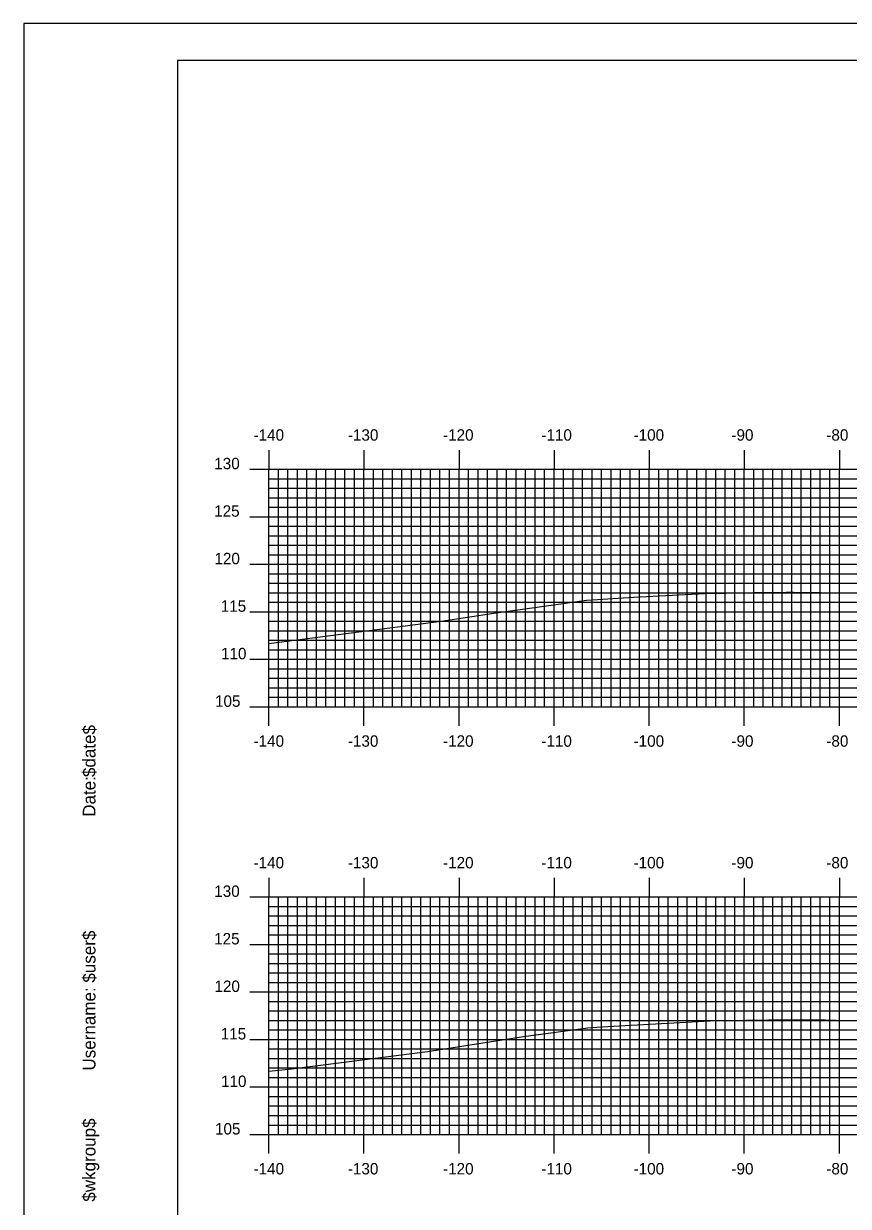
# Model space of a CAD drawing. Extents: x 855468 to 855811, y 366605 to 366825.
# Drawn here: x 855467.8 to 855554.5, y 366700.5 to 366824.9 of the extents above; entities that cross this region are included whole.
import ezdxf

# ---------------------------------------------------------------- set-up
doc = ezdxf.new("R2010")
doc.units = 0
for name, color, linetype in [('BORDER', 7, 'Continuous'), ('H_V ANNOTATION', 7, 'Continuous'), ('M_Roadway_Centerline', 7, 'Continuous'), ('MAJOR', 7, 'Continuous'), ('MINOR', 7, 'Continuous'), ('PLOT BOUNDARY', 7, 'Continuous'), ('S_Roadway_Centerline', 7, 'Continuous')]:
    doc.layers.add(name, color=color, linetype=linetype)

msp = doc.modelspace()

# ---------------------------------------------------------------- linework, layer by layer
at = {"layer": 'BORDER'}
msp.add_lwpolyline([(855483.98, 366611.06), (855803.98, 366611.06), (855803.98, 366821.06), (855483.98, 366821.06)], close=True, dxfattribs=at)
at = {"layer": 'MAJOR'}
for p, q in [((855493.58, 366780.06), (855493.58, 366778.06)), ((855503.58, 366780.06), (855503.58, 366778.06)), ((855513.58, 366780.06), (855513.58, 366778.06)), ((855523.58, 366780.06), (855523.58, 366778.06)), ((855533.58, 366780.06), (855533.58, 366778.06)), ((855543.58, 366780.06), (855543.58, 366778.06)), ((855553.58, 366780.06), (855553.58, 366778.06)), ((855491.58, 366778.06), (855493.58, 366778.06)), ((855493.58, 366778.06), (855773.58, 366778.06)), ((855493.58, 366753.06), (855493.58, 366778.06)), ((855493.58, 366753.06), (855493.58, 366778.06)), ((855493.58, 366778.06), (855773.58, 366778.06)), ((855503.58, 366753.06), (855503.58, 366778.06)), ((855513.58, 366753.06), (855513.58, 366778.06)), ((855523.58, 366753.06), (855523.58, 366778.06)), ((855533.58, 366753.06), (855533.58, 366778.06)), ((855543.58, 366753.06), (855543.58, 366778.06)), ((855553.58, 366753.06), (855553.58, 366778.06)), ((855491.58, 366773.06), (855493.58, 366773.06)), ((855493.58, 366773.06), (855773.58, 366773.06)), ((855491.58, 366768.06), (855493.58, 366768.06)), ((855493.58, 366768.06), (855773.58, 366768.06)), ((855491.58, 366763.06), (855493.58, 366763.06)), ((855493.58, 366763.06), (855773.58, 366763.06)), ((855491.58, 366758.06), (855493.58, 366758.06)), ((855493.58, 366758.06), (855773.58, 366758.06)), ((855491.58, 366753.06), (855493.58, 366753.06)), ((855493.58, 366753.06), (855773.58, 366753.06)), ((855493.58, 366753.06), (855773.58, 366753.06)), ((855493.58, 366751.05), (855493.58, 366753.06)), ((855503.58, 366751.05), (855503.58, 366753.06)), ((855513.58, 366751.05), (855513.58, 366753.06)), ((855523.58, 366751.05), (855523.58, 366753.06)), ((855533.58, 366751.05), (855533.58, 366753.06)), ((855543.58, 366751.05), (855543.58, 366753.06)), ((855553.58, 366751.05), (855553.58, 366753.06)), ((855493.58, 366735.06), (855493.58, 366733.06)), ((855503.58, 366735.06), (855503.58, 366733.06)), ((855513.58, 366735.06), (855513.58, 366733.06)), ((855523.58, 366735.06), (855523.58, 366733.06)), ((855533.58, 366735.06), (855533.58, 366733.06)), ((855543.58, 366735.06), (855543.58, 366733.06)), ((855553.58, 366735.06), (855553.58, 366733.06)), ((855491.58, 366733.06), (855493.58, 366733.06)), ((855493.58, 366733.06), (855773.58, 366733.06)), ((855493.58, 366708.06), (855493.58, 366733.06)), ((855493.58, 366708.06), (855493.58, 366733.06)), ((855493.58, 366733.06), (855773.58, 366733.06)), ((855503.58, 366708.06), (855503.58, 366733.06)), ((855513.58, 366708.06), (855513.58, 366733.06)), ((855523.58, 366708.06), (855523.58, 366733.06)), ((855533.58, 366708.06), (855533.58, 366733.06)), ((855543.58, 366708.06), (855543.58, 366733.06)), ((855553.58, 366708.06), (855553.58, 366733.06)), ((855491.58, 366728.06), (855493.58, 366728.06)), ((855493.58, 366728.06), (855773.58, 366728.06)), ((855491.58, 366723.06), (855493.58, 366723.06)), ((855493.58, 366723.06), (855773.58, 366723.06)), ((855491.58, 366718.06), (855493.58, 366718.06)), ((855493.58, 366718.06), (855773.58, 366718.06)), ((855491.58, 366713.06), (855493.58, 366713.06)), ((855493.58, 366713.06), (855773.58, 366713.06)), ((855491.58, 366708.06), (855493.58, 366708.06)), ((855493.58, 366708.06), (855773.58, 366708.06)), ((855493.58, 366708.06), (855773.58, 366708.06)), ((855493.58, 366706.05), (855493.58, 366708.06)), ((855503.58, 366706.05), (855503.58, 366708.06)), ((855513.58, 366706.05), (855513.58, 366708.06)), ((855523.58, 366706.05), (855523.58, 366708.06)), ((855533.58, 366706.05), (855533.58, 366708.06)), ((855543.58, 366706.05), (855543.58, 366708.06)), ((855553.58, 366706.05), (855553.58, 366708.06))]:
    msp.add_line(p, q, dxfattribs=at)
at = {"layer": 'MINOR'}
for p, q in [((855494.58, 366753.06), (855494.58, 366778.06)), ((855495.58, 366753.06), (855495.58, 366778.06)), ((855496.58, 366753.06), (855496.58, 366778.06)), ((855497.58, 366753.06), (855497.58, 366778.06)), ((855498.58, 366753.06), (855498.58, 366778.06)), ((855499.58, 366753.06), (855499.58, 366778.06)), ((855500.58, 366753.06), (855500.58, 366778.06)), ((855501.58, 366753.06), (855501.58, 366778.06)), ((855502.58, 366753.06), (855502.58, 366778.06)), ((855504.58, 366753.06), (855504.58, 366778.06)), ((855505.58, 366753.06), (855505.58, 366778.06)), ((855506.58, 366753.06), (855506.58, 366778.06)), ((855507.58, 366753.06), (855507.58, 366778.06)), ((855508.58, 366753.06), (855508.58, 366778.06)), ((855509.58, 366753.06), (855509.58, 366778.06)), ((855510.58, 366753.06), (855510.58, 366778.06)), ((855511.58, 366753.06), (855511.58, 366778.06)), ((855512.58, 366753.06), (855512.58, 366778.06)), ((855514.58, 366753.06), (855514.58, 366778.06)), ((855515.58, 366753.06), (855515.58, 366778.06)), ((855516.58, 366753.06), (855516.58, 366778.06)), ((855517.58, 366753.06), (855517.58, 366778.06)), ((855518.58, 366753.06), (855518.58, 366778.06)), ((855519.58, 366753.06), (855519.58, 366778.06)), ((855520.58, 366753.06), (855520.58, 366778.06)), ((855521.58, 366753.06), (855521.58, 366778.06)), ((855522.58, 366753.06), (855522.58, 366778.06)), ((855524.58, 366753.06), (855524.58, 366778.06)), ((855525.58, 366753.06), (855525.58, 366778.06)), ((855526.58, 366753.06), (855526.58, 366778.06)), ((855527.58, 366753.06), (855527.58, 366778.06)), ((855528.58, 366753.06), (855528.58, 366778.06)), ((855529.58, 366753.06), (855529.58, 366778.06)), ((855530.58, 366753.06), (855530.58, 366778.06)), ((855531.58, 366753.06), (855531.58, 366778.06)), ((855532.58, 366753.06), (855532.58, 366778.06)), ((855534.58, 366753.06), (855534.58, 366778.06)), ((855535.58, 366753.06), (855535.58, 366778.06)), ((855536.58, 366753.06), (855536.58, 366778.06)), ((855537.58, 366753.06), (855537.58, 366778.06)), ((855538.58, 366753.06), (855538.58, 366778.06)), ((855539.58, 366753.06), (855539.58, 366778.06)), ((855540.58, 366753.06), (855540.58, 366778.06)), ((855541.58, 366753.06), (855541.58, 366778.06)), ((855542.58, 366753.06), (855542.58, 366778.06)), ((855544.58, 366753.06), (855544.58, 366778.06)), ((855545.58, 366753.06), (855545.58, 366778.06)), ((855546.58, 366753.06), (855546.58, 366778.06)), ((855547.58, 366753.06), (855547.58, 366778.06)), ((855548.58, 366753.06), (855548.58, 366778.06)), ((855549.58, 366753.06), (855549.58, 366778.06)), ((855550.58, 366753.06), (855550.58, 366778.06)), ((855551.58, 366753.06), (855551.58, 366778.06)), ((855552.58, 366753.06), (855552.58, 366778.06)), ((855493.58, 366777.06), (855773.58, 366777.06)), ((855493.58, 366777.06), (855495.59, 366777.06)), ((855493.58, 366776.06), (855773.58, 366776.06)), ((855493.58, 366776.06), (855495.59, 366776.06)), ((855493.58, 366775.06), (855773.58, 366775.06)), ((855493.58, 366775.06), (855495.59, 366775.06)), ((855493.58, 366774.06), (855773.58, 366774.06)), ((855493.58, 366774.06), (855495.59, 366774.06)), ((855493.58, 366772.06), (855773.58, 366772.06)), ((855493.58, 366772.06), (855495.59, 366772.06)), ((855493.58, 366771.06), (855773.58, 366771.06)), ((855493.58, 366771.06), (855495.59, 366771.06)), ((855493.58, 366770.06), (855773.58, 366770.06)), ((855493.58, 366770.06), (855495.59, 366770.06)), ((855493.58, 366769.06), (855773.58, 366769.06)), ((855493.58, 366769.06), (855495.59, 366769.06)), ((855493.58, 366767.06), (855773.58, 366767.06)), ((855493.58, 366767.06), (855495.59, 366767.06)), ((855493.58, 366766.06), (855773.58, 366766.06)), ((855493.58, 366766.06), (855495.59, 366766.06)), ((855493.58, 366765.06), (855773.58, 366765.06)), ((855493.58, 366765.06), (855495.59, 366765.06)), ((855493.58, 366764.06), (855773.58, 366764.06)), ((855493.58, 366764.06), (855495.59, 366764.06)), ((855493.58, 366762.06), (855773.58, 366762.06)), ((855493.58, 366762.06), (855495.59, 366762.06)), ((855493.58, 366761.06), (855773.58, 366761.06)), ((855493.58, 366761.06), (855495.59, 366761.06)), ((855493.58, 366760.06), (855773.58, 366760.06)), ((855493.58, 366760.06), (855495.59, 366760.06)), ((855493.58, 366759.06), (855773.58, 366759.06)), ((855493.58, 366759.06), (855495.59, 366759.06)), ((855493.58, 366757.06), (855773.58, 366757.06)), ((855493.58, 366757.06), (855495.59, 366757.06)), ((855493.58, 366756.06), (855773.58, 366756.06)), ((855493.58, 366756.06), (855495.59, 366756.06)), ((855493.58, 366755.06), (855773.58, 366755.06)), ((855493.58, 366755.06), (855495.59, 366755.06)), ((855493.58, 366754.06), (855773.58, 366754.06)), ((855493.58, 366754.06), (855495.59, 366754.06)), ((855494.58, 366708.06), (855494.58, 366733.06)), ((855495.58, 366708.06), (855495.58, 366733.06)), ((855496.58, 366708.06), (855496.58, 366733.06)), ((855497.58, 366708.06), (855497.58, 366733.06)), ((855498.58, 366708.06), (855498.58, 366733.06)), ((855499.58, 366708.06), (855499.58, 366733.06)), ((855500.58, 366708.06), (855500.58, 366733.06)), ((855501.58, 366708.06), (855501.58, 366733.06)), ((855502.58, 366708.06), (855502.58, 366733.06)), ((855504.58, 366708.06), (855504.58, 366733.06)), ((855505.58, 366708.06), (855505.58, 366733.06)), ((855506.58, 366708.06), (855506.58, 366733.06)), ((855507.58, 366708.06), (855507.58, 366733.06)), ((855508.58, 366708.06), (855508.58, 366733.06)), ((855509.58, 366708.06), (855509.58, 366733.06)), ((855510.58, 366708.06), (855510.58, 366733.06)), ((855511.58, 366708.06), (855511.58, 366733.06)), ((855512.58, 366708.06), (855512.58, 366733.06)), ((855514.58, 366708.06), (855514.58, 366733.06)), ((855515.58, 366708.06), (855515.58, 366733.06)), ((855516.58, 366708.06), (855516.58, 366733.06)), ((855517.58, 366708.06), (855517.58, 366733.06)), ((855518.58, 366708.06), (855518.58, 366733.06)), ((855519.58, 366708.06), (855519.58, 366733.06)), ((855520.58, 366708.06), (855520.58, 366733.06)), ((855521.58, 366708.06), (855521.58, 366733.06)), ((855522.58, 366708.06), (855522.58, 366733.06)), ((855524.58, 366708.06), (855524.58, 366733.06)), ((855525.58, 366708.06), (855525.58, 366733.06)), ((855526.58, 366708.06), (855526.58, 366733.06)), ((855527.58, 366708.06), (855527.58, 366733.06)), ((855528.58, 366708.06), (855528.58, 366733.06)), ((855529.58, 366708.06), (855529.58, 366733.06)), ((855530.58, 366708.06), (855530.58, 366733.06)), ((855531.58, 366708.06), (855531.58, 366733.06)), ((855532.58, 366708.06), (855532.58, 366733.06)), ((855534.58, 366708.06), (855534.58, 366733.06)), ((855535.58, 366708.06), (855535.58, 366733.06)), ((855536.58, 366708.06), (855536.58, 366733.06)), ((855537.58, 366708.06), (855537.58, 366733.06)), ((855538.58, 366708.06), (855538.58, 366733.06)), ((855539.58, 366708.06), (855539.58, 366733.06)), ((855540.58, 366708.06), (855540.58, 366733.06)), ((855541.58, 366708.06), (855541.58, 366733.06)), ((855542.58, 366708.06), (855542.58, 366733.06)), ((855544.58, 366708.06), (855544.58, 366733.06)), ((855545.58, 366708.06), (855545.58, 366733.06)), ((855546.58, 366708.06), (855546.58, 366733.06)), ((855547.58, 366708.06), (855547.58, 366733.06)), ((855548.58, 366708.06), (855548.58, 366733.06)), ((855549.58, 366708.06), (855549.58, 366733.06)), ((855550.58, 366708.06), (855550.58, 366733.06)), ((855551.58, 366708.06), (855551.58, 366733.06)), ((855552.58, 366708.06), (855552.58, 366733.06)), ((855493.58, 366732.06), (855773.58, 366732.06)), ((855493.58, 366732.06), (855495.59, 366732.06)), ((855493.58, 366731.06), (855773.58, 366731.06)), ((855493.58, 366731.06), (855495.59, 366731.06)), ((855493.58, 366730.06), (855773.58, 366730.06)), ((855493.58, 366730.06), (855495.59, 366730.06)), ((855493.58, 366729.06), (855773.58, 366729.06)), ((855493.58, 366729.06), (855495.59, 366729.06)), ((855493.58, 366727.06), (855773.58, 366727.06)), ((855493.58, 366727.06), (855495.59, 366727.06)), ((855493.58, 366726.06), (855773.58, 366726.06)), ((855493.58, 366726.06), (855495.59, 366726.06)), ((855493.58, 366725.06), (855773.58, 366725.06)), ((855493.58, 366725.06), (855495.59, 366725.06)), ((855493.58, 366724.06), (855773.58, 366724.06)), ((855493.58, 366724.06), (855495.59, 366724.06)), ((855493.58, 366722.06), (855773.58, 366722.06)), ((855493.58, 366722.06), (855495.59, 366722.06)), ((855493.58, 366721.06), (855773.58, 366721.06)), ((855493.58, 366721.06), (855495.59, 366721.06)), ((855493.58, 366720.06), (855773.58, 366720.06)), ((855493.58, 366720.06), (855495.59, 366720.06)), ((855493.58, 366719.06), (855773.58, 366719.06)), ((855493.58, 366719.06), (855495.59, 366719.06)), ((855493.58, 366717.06), (855773.58, 366717.06)), ((855493.58, 366717.06), (855495.59, 366717.06)), ((855493.58, 366716.06), (855773.58, 366716.06)), ((855493.58, 366716.06), (855495.59, 366716.06)), ((855493.58, 366715.06), (855773.58, 366715.06)), ((855493.58, 366715.06), (855495.59, 366715.06)), ((855493.58, 366714.06), (855773.58, 366714.06)), ((855493.58, 366714.06), (855495.59, 366714.06)), ((855493.58, 366712.06), (855773.58, 366712.06)), ((855493.58, 366712.06), (855495.59, 366712.06)), ((855493.58, 366711.06), (855773.58, 366711.06)), ((855493.58, 366711.06), (855495.59, 366711.06)), ((855493.58, 366710.06), (855773.58, 366710.06)), ((855493.58, 366710.06), (855495.59, 366710.06)), ((855493.58, 366709.06), (855773.58, 366709.06)), ((855493.58, 366709.06), (855495.59, 366709.06))]:
    msp.add_line(p, q, dxfattribs=at)
at = {"layer": 'PLOT BOUNDARY'}
msp.add_lwpolyline([(855467.8, 366604.94), (855807.8, 366604.94), (855807.8, 366824.94), (855467.8, 366824.94)], close=True, dxfattribs=at)
at = {"layer": 'S_Roadway_Centerline'}
for points in [[(855493.58, 366759.73), (855511.69, 366762.07), (855517.23, 366762.93), (855525.04, 366764), (855527, 366764.27), (855527.6, 366764.31), (855531.98, 366764.58), (855539.4, 366764.99), (855543.97, 366765.06), (855544.64, 366765.08), (855548, 366765.13), (855548.76, 366765.12), (855551.52, 366765.1), (855551.67, 366765.1), (855562.93, 366764.96)], [(855493.58, 366714.73), (855496, 366714.96), (855510.25, 366716.8), (855520.36, 366718.37), (855527.12, 366719.3), (855527.48, 366719.32), (855530.41, 366719.5), (855539.99, 366720.02), (855543.76, 366720.08), (855544.31, 366720.1), (855548.02, 366720.15), (855548.85, 366720.13), (855551.48, 366720.12), (855552.11, 366720.12), (855554.41, 366720.07), (855563.42, 366719.96)]]:
    msp.add_lwpolyline(points, dxfattribs=at)

# ---------------------------------------------------------------- texts
at = {"layer": 'BORDER'}
for s, p in [('$date$', (855475.35, 366745.67)), ('Date:', (855475.35, 366741.49)), ('$user$', (855475.35, 366724.04)), ('Username:', (855475.35, 366714.79)), ('$wkgroup$', (855475.35, 366700.99))]:
    msp.add_text(s, height=1.339, rotation=90, dxfattribs=at).set_placement(p)
at = {"layer": 'H_V ANNOTATION'}
for s, p in [('-140', (855491.97, 366781.06)), ('-130', (855501.89, 366781.06)), ('-120', (855511.9, 366781.06)), ('-110', (855522.24, 366781.06)), ('-100', (855531.94, 366781.06)), ('-90', (855542.23, 366781.06)), ('-80', (855552.21, 366781.06)), ('130', (855487.84, 366778.06)), ('125', (855487.83, 366773.06)), ('120', (855487.86, 366768.06)), ('115', (855488.52, 366763.06)), ('110', (855488.55, 366758.06)), ('105', (855487.92, 366753.06)), ('-140', (855491.97, 366748.86)), ('-130', (855501.89, 366748.86)), ('-120', (855511.9, 366748.86)), ('-110', (855522.24, 366748.86)), ('-100', (855531.94, 366748.86)), ('-90', (855542.23, 366748.86)), ('-80', (855552.21, 366748.86)), ('-140', (855491.97, 366736.06)), ('-130', (855501.89, 366736.06)), ('-120', (855511.9, 366736.06)), ('-110', (855522.24, 366736.06)), ('-100', (855531.94, 366736.06)), ('-90', (855542.23, 366736.06)), ('-80', (855552.21, 366736.06)), ('130', (855487.84, 366733.06)), ('125', (855487.83, 366728.06)), ('120', (855487.86, 366723.06)), ('115', (855488.52, 366718.06)), ('110', (855488.55, 366713.06)), ('105', (855487.92, 366708.06)), ('-140', (855491.97, 366703.86)), ('-130', (855501.89, 366703.86)), ('-120', (855511.9, 366703.86)), ('-110', (855522.24, 366703.86)), ('-100', (855531.94, 366703.86)), ('-90', (855542.23, 366703.86)), ('-80', (855552.21, 366703.86))]:
    msp.add_text(s, height=1.2, dxfattribs=at).set_placement(p)
at = {"layer": 'M_Roadway_Centerline'}
for s, p in [('C', (855548.76, 366765.12)), ('L', (855548.76, 366765.11)), ('C', (855548.85, 366720.13)), ('L', (855548.85, 366720.13))]:
    msp.add_text(s, height=0.0146, dxfattribs=at).set_placement(p)
at = {"layer": 'MAJOR'}
for p in [(855493.57, 366753.06), (855493.57, 366708.06)]:
    msp.add_text('-', height=0.012, dxfattribs=at).set_placement(p)

doc.saveas('drawing.dxf')
